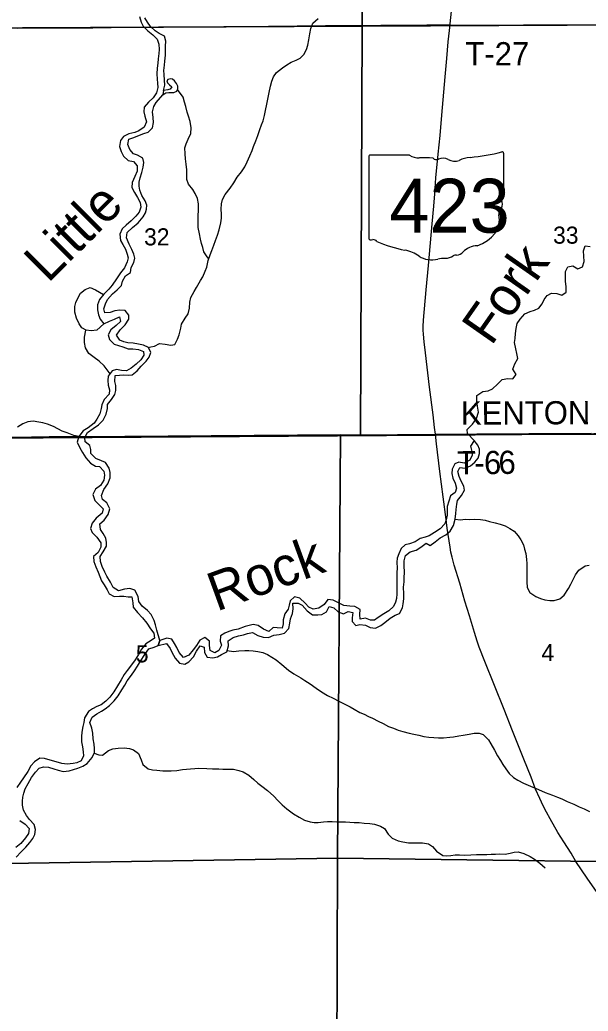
# Model space of a CAD drawing. Extents: x 1584893 to 1934202, y 663575 to 1091909.
# Drawn here: x 1783850 to 1791189, y 956462 to 969270 of the extents above; entities that cross this region are included whole.
import ezdxf

# ---------------------------------------------------------------- set-up
doc = ezdxf.new("R2010")
doc.units = 0
for name, color, linetype in [('GM_X_County_Road', 7, 'Continuous'), ('GM_X_Major_River', 7, 'Continuous'), ('GM_X_Major_River_Text', 7, 'Continuous'), ('GM_X_Minor_River', 7, 'Continuous'), ('GM_X_Minor_River_Text', 7, 'Continuous'), ('GM_X_Section', 7, 'Continuous'), ('GM_X_Section_Text', 7, 'Continuous'), ('GM_X_State_Location', 7, 'Continuous'), ('GM_X_State_Route', 7, 'Continuous'), ('GM_X_State_Shield', 7, 'Continuous'), ('GM_X_Township', 7, 'Continuous'), ('GM_X_Township_Road', 7, 'Continuous'), ('GM_X_Township_Road_Text', 7, 'Continuous')]:
    doc.layers.add(name, color=color, linetype=linetype)

msp = doc.modelspace()

# ---------------------------------------------------------------- linework, layer by layer
at = {"layer": 'GM_X_County_Road'}
for points in [[(1783824, 969162), (1784272, 969167), (1784527, 969169), (1784793, 969169), (1785030, 969172), (1785384, 969174), (1785703, 969176), (1786065, 969181), (1786486, 969184), (1786779, 969186), (1787060, 969189), (1787430, 969192), (1787798, 969196), (1788111, 969198), (1788512, 969201), (1789106, 969205), (1789300, 969205), (1789365, 969205), (1789406, 969205)], [(1781619, 963852), (1781621, 963852), (1781735, 963853), (1782030, 963855), (1782178, 963857), (1782375, 963858), (1782885, 963865), (1782998, 963866), (1783259, 963870), (1783766, 963878), (1784229, 963886), (1784853, 963887), (1785298, 963887), (1786047, 963891), (1786409, 963894), (1786805, 963898), (1787527, 963903), (1787855, 963906), (1788059, 963907), (1788529, 963910), (1788725, 963914), (1789216, 963917)]]:
    msp.add_lwpolyline(points, dxfattribs=at)
at = {"layer": 'GM_X_Major_River'}
for points in [[(1785394, 969315), (1785417, 969241), (1785443, 969190), (1785503, 969126), (1785568, 969075), (1785624, 969019), (1785644, 968958), (1785647, 968886), (1785643, 968834), (1785636, 968766), (1785630, 968712), (1785625, 968646), (1785621, 968574), (1785624, 968502), (1785628, 968452), (1785631, 968395), (1785613, 968325), (1785570, 968262), (1785512, 968206), (1785457, 968144), (1785451, 968080), (1785466, 968026), (1785484, 967954), (1785455, 967884), (1785385, 967838), (1785333, 967816), (1785259, 967799), (1785188, 967765), (1785148, 967713), (1785135, 967635), (1785157, 967571), (1785190, 967511), (1785248, 967454), (1785318, 967438), (1785366, 967383), (1785365, 967317), (1785337, 967245), (1785302, 967167), (1785297, 967103), (1785331, 967039), (1785369, 966976), (1785404, 966912), (1785412, 966852), (1785389, 966784), (1785347, 966732), (1785288, 966674), (1785222, 966617), (1785171, 966571), (1785143, 966501), (1785150, 966419), (1785178, 966368), (1785213, 966308), (1785235, 966244), (1785247, 966194), (1785238, 966142), (1785200, 966068), (1785149, 966000), (1785100, 965922), (1785044, 965842), (1784999, 965789), (1784933, 965725), (1784878, 965657), (1784852, 965587), (1784851, 965525), (1784865, 965461), (1784886, 965403), (1784936, 965342), (1785006, 965376), (1785073, 965401), (1785139, 965435), (1785150, 965371), (1785094, 965319)], [(1785705, 968359), (1785722, 968427), (1785718, 968489), (1785715, 968563), (1785711, 968617), (1785718, 968685), (1785724, 968735), (1785729, 968812), (1785731, 968862), (1785733, 968932), (1785736, 968996), (1785716, 969060), (1785649, 969095), (1785597, 969127), (1785539, 969186), (1785500, 969238), (1785464, 969294)], [(1785697, 968302), (1785737, 968325), (1785773, 968332), (1785803, 968332), (1785837, 968330), (1785877, 968348), (1785889, 968380), (1785890, 968412), (1785872, 968446), (1785848, 968482), (1785820, 968502), (1785800, 968510), (1785760, 968499), (1785746, 968481), (1785756, 968457), (1785782, 968432), (1785814, 968406), (1785793, 968374), (1785775, 968372), (1785761, 968368), (1785705, 968359)], [(1784934, 963204), (1784987, 963276), (1785017, 963352), (1785016, 963424), (1785004, 963480), (1784955, 963552), (1784903, 963571), (1784833, 963603), (1784765, 963668), (1784766, 963720), (1784752, 963772), (1784692, 963819), (1784689, 963875), (1784725, 963937), (1784796, 963990), (1784864, 964038), (1784927, 964098), (1784963, 964176), (1784980, 964248), (1784984, 964302), (1785035, 964367), (1785077, 964431), (1785088, 964483), (1785088, 964545), (1785075, 964596), (1785083, 964676), (1785135, 964679), (1785185, 964685), (1785249, 964681), (1785299, 964684), (1785364, 964734), (1785418, 964796), (1785483, 964859), (1785521, 964911), (1785542, 964971), (1785510, 965038), (1785448, 965066), (1785384, 965082), (1785314, 965095), (1785246, 965099), (1785194, 965108), (1785141, 965130), (1785097, 965197), (1785146, 965266), (1785208, 965330), (1785259, 965402), (1785257, 965454), (1785211, 965513), (1785141, 965521), (1785075, 965511), (1785015, 965490), (1784947, 965484), (1784933, 965535), (1784954, 965603), (1784982, 965658), (1785045, 965730), (1785105, 965782), (1785164, 965840), (1785176, 965896), (1785215, 965961), (1785277, 966007), (1785288, 966069), (1785320, 966137), (1785333, 966189), (1785323, 966241), (1785295, 966304), (1785260, 966374), (1785227, 966454), (1785237, 966522), (1785306, 966588), (1785378, 966648), (1785441, 966723), (1785473, 966775), (1785486, 966825), (1785488, 966877), (1785470, 966930), (1785427, 967002), (1785399, 967068), (1785392, 967121), (1785390, 967175), (1785404, 967227), (1785427, 967297), (1785444, 967367), (1785452, 967425), (1785440, 967481), (1785371, 967523), (1785319, 967540), (1785269, 967596), (1785244, 967661), (1785256, 967727), (1785324, 967752), (1785395, 967780), (1785449, 967801), (1785505, 967819), (1785563, 967873), (1785578, 967945), (1785570, 968007), (1785563, 968081), (1785581, 968149), (1785612, 968201), (1785697, 968302)], [(1785705, 968359), (1785697, 968302)], [(1785094, 965319), (1785023, 965265), (1784989, 965199), (1785009, 965139), (1785068, 965079), (1785124, 965064), (1785180, 965046), (1785248, 965021), (1785308, 965019), (1785382, 965010), (1785446, 964986), (1785451, 964936), (1785411, 964876), (1785352, 964820), (1785288, 964771), (1785226, 964735), (1785162, 964739), (1785096, 964754), (1785044, 964734), (1784991, 964668), (1784987, 964610), (1784990, 964552), (1785006, 964490), (1785005, 964434), (1784937, 964364), (1784908, 964298), (1784900, 964248), (1784885, 964178), (1784845, 964112), (1784810, 964060), (1784734, 963997), (1784667, 963959), (1784611, 963889), (1784592, 963813), (1784626, 963741), (1784657, 963679), (1784701, 963612), (1784762, 963542), (1784828, 963503), (1784880, 963499), (1784934, 963440), (1784943, 963388), (1784935, 963322), (1784892, 963256), (1784828, 963207), (1784793, 963137), (1784819, 963062), (1784926, 962953), (1784912, 962895), (1784835, 962832), (1784785, 962766), (1784764, 962698), (1784784, 962648), (1784843, 962587), (1784895, 962515), (1784896, 962457), (1784860, 962389), (1784801, 962337), (1784805, 962271), (1784830, 962203), (1784860, 962134), (1784884, 962078), (1784905, 962024), (1784939, 961969), (1784976, 961907), (1785002, 961853), (1785066, 961818), (1785138, 961822), (1785192, 961823), (1785248, 961815), (1785298, 961815), (1785309, 961736), (1785315, 961680), (1785369, 961614), (1785434, 961543), (1785492, 961474), (1785539, 961402), (1785579, 961348), (1785588, 961280), (1785544, 961250), (1785476, 961208), (1785421, 961140), (1785384, 961072), (1785340, 961003), (1785277, 960921), (1785235, 960865), (1785198, 960813), (1785160, 960743), (1785111, 960664), (1785065, 960590), (1785010, 960520), (1784962, 960468), (1784899, 960421), (1784845, 960397), (1784789, 960369), (1784736, 960335), (1784686, 960254), (1784675, 960194), (1784663, 960140), (1784650, 960066), (1784644, 960013)], [(1785656, 961253), (1785619, 961385), (1785600, 961454), (1785584, 961510), (1785544, 961588), (1785499, 961639), (1785431, 961693), (1785386, 961756), (1785376, 961820), (1785335, 961900), (1785271, 961925), (1785203, 961913), (1785126, 961892), (1785057, 961934), (1785021, 962007), (1784974, 962083), (1784946, 962136), (1784915, 962206), (1784891, 962270), (1784887, 962338), (1784926, 962398), (1784967, 962468), (1784969, 962518), (1784959, 962572), (1784928, 962635), (1784892, 962685), (1784883, 962757), (1784937, 962807), (1784992, 962879), (1785010, 962953), (1784975, 963029), (1784917, 963072), (1784905, 963124), (1784934, 963204)], [(1785636, 961186), (1785656, 961253)], [(1783802, 958452), (1783866, 958522), (1783927, 958580), (1783979, 958641), (1784016, 958695), (1784044, 958747), (1784050, 958811), (1784035, 958873), (1783973, 958940), (1783934, 958990), (1783896, 959061), (1783885, 959125), (1783883, 959175), (1783889, 959227), (1783900, 959281), (1783918, 959335), (1783957, 959405), (1783999, 959481), (1784052, 959549), (1784100, 959602), (1784157, 959620), (1784221, 959614), (1784288, 959593), (1784344, 959575), (1784410, 959560), (1784488, 959568), (1784541, 959583), (1784597, 959601), (1784663, 959627), (1784719, 959662), (1784782, 959738), (1784814, 959804), (1784813, 959858), (1784809, 959912), (1784796, 959980), (1784792, 960053), (1784781, 960119), (1784755, 960193), (1784784, 960261), (1784846, 960305), (1784903, 960340), (1784953, 960370), (1785007, 960412), (1785070, 960473), (1785118, 960535), (1785169, 960613), (1785205, 960675), (1785238, 960729), (1785292, 960803), (1785331, 960858), (1785371, 960918), (1785408, 960986), (1785463, 961070), (1785517, 961142), (1785583, 961167), (1785636, 961186)], [(1784644, 960013), (1784645, 959943), (1784659, 959879), (1784668, 959815), (1784674, 959761), (1784640, 959697), (1784587, 959671), (1784537, 959662), (1784461, 959654), (1784393, 959661), (1784321, 959685), (1784241, 959706), (1784169, 959726), (1784107, 959729), (1784039, 959685), (1783992, 959633), (1783954, 959559), (1783899, 959478), (1783857, 959422), (1783812, 959352)], [(1783849, 958925), (1783919, 958878), (1783970, 958824), (1783960, 958756), (1783923, 958702), (1783863, 958630), (1783800, 958576)]]:
    msp.add_lwpolyline(points, dxfattribs=at)
at = {"layer": 'GM_X_Minor_River'}
for points in [[(1785508, 965039), (1785540, 965047), (1785590, 965055), (1785655, 965089), (1785727, 965078), (1785799, 965066), (1785853, 965075), (1785887, 965145), (1785906, 965201), (1785928, 965287), (1785939, 965337), (1785987, 965417), (1786022, 965471), (1786040, 965547), (1786045, 965623), (1786060, 965683), (1786100, 965761), (1786133, 965813), (1786181, 965901), (1786214, 965952), (1786244, 966024), (1786263, 966076), (1786283, 966162), (1786306, 966232), (1786328, 966290), (1786357, 966358), (1786377, 966418), (1786404, 966490), (1786426, 966556), (1786445, 966646), (1786452, 966706), (1786454, 966760), (1786450, 966825), (1786455, 966891), (1786465, 966947), (1786502, 967013), (1786565, 967094), (1786613, 967164), (1786658, 967236), (1786714, 967306), (1786755, 967370), (1786787, 967435), (1786820, 967515), (1786848, 967583), (1786869, 967635), (1786897, 967705), (1786924, 967777), (1786951, 967853), (1786971, 967913), (1786991, 967967), (1787008, 968035), (1787022, 968101), (1787039, 968179), (1787054, 968247), (1787070, 968333), (1787087, 968413), (1787105, 968477), (1787126, 968533), (1787166, 968589), (1787243, 968649), (1787297, 968688), (1787355, 968722), (1787418, 968750), (1787468, 968777), (1787518, 968823), (1787551, 968885), (1787571, 968943), (1787582, 969013), (1787594, 969089), (1787607, 969159), (1787635, 969227), (1787702, 969287)], [(1786290, 966182), (1786270, 966209), (1786228, 966273), (1786212, 966327), (1786197, 966379), (1786183, 966438), (1786170, 966504), (1786154, 966588), (1786153, 966660), (1786153, 966736), (1786156, 966811), (1786159, 966891), (1786143, 966961), (1786116, 967027), (1786082, 967078), (1786028, 967148), (1786007, 967206), (1786008, 967333), (1785998, 967407), (1785989, 967475), (1785985, 967541), (1785982, 967617), (1785996, 967669), (1786025, 967729), (1786057, 967803), (1786064, 967875), (1786050, 967958), (1786029, 968024), (1786009, 968078), (1785994, 968152), (1785978, 968207), (1785961, 968269), (1785886, 968370)], [(1789717, 963836), (1789632, 963927), (1789628, 963977), (1789695, 964046), (1789749, 964118), (1789774, 964202), (1789762, 964278), (1789753, 964345), (1789753, 964415), (1789828, 964468), (1789896, 964478), (1789952, 964501), (1790019, 964561), (1790079, 964625), (1790151, 964636), (1790215, 964634), (1790260, 964686), (1790218, 964758), (1790243, 964826), (1790281, 964894), (1790270, 964958), (1790256, 965020), (1790239, 965101), (1790245, 965153), (1790252, 965219), (1790258, 965283), (1790273, 965349), (1790313, 965405), (1790372, 965472), (1790440, 965502), (1790498, 965520), (1790551, 965543), (1790595, 965601), (1790621, 965655), (1790658, 965707), (1790716, 965739), (1790784, 965734), (1790848, 965714), (1790904, 965751), (1790905, 965821), (1790897, 965896), (1790896, 965962), (1790898, 966020), (1790927, 966078), (1790991, 966091), (1791055, 966053), (1791117, 966077), (1791138, 966147), (1791134, 966217), (1791129, 966287), (1791149, 966351), (1791217, 966340)], [(1784936, 965342), (1784845, 965259), (1784773, 965251), (1784705, 965260), (1784651, 965292), (1784616, 965342), (1784582, 965417), (1784559, 965493), (1784559, 965565), (1784574, 965617), (1784598, 965673), (1784633, 965737), (1784695, 965787), (1784759, 965810), (1784825, 965780), (1784929, 965720)], [(1785015, 964698), (1784989, 964733), (1784938, 964799), (1784874, 964862), (1784811, 964906), (1784743, 964961), (1784699, 965031), (1784686, 965101), (1784684, 965170), (1784701, 965262)], [(1784610, 963887), (1784545, 963900), (1784461, 963933), (1784397, 963957), (1784341, 963988), (1784283, 964016), (1784206, 964047), (1784148, 964063), (1784094, 964073), (1784020, 964084), (1783952, 964076), (1783889, 964051), (1783819, 964009)], [(1789717, 963836), (1789670, 963760)], [(1789786, 963723), (1789765, 963775), (1789717, 963836)], [(1785636, 961186), (1785744, 961212), (1785791, 961150), (1785813, 961100), (1785855, 961025), (1785910, 960959), (1785980, 960946), (1786032, 960974), (1786093, 961041), (1786133, 961115), (1786178, 961183), (1786230, 961167), (1786235, 961097), (1786271, 961036), (1786341, 961028), (1786401, 961041), (1786455, 961069), (1786522, 961107), (1786544, 961183), (1786539, 961245), (1786605, 961288), (1786675, 961312), (1786740, 961326), (1786790, 961341), (1786856, 961353), (1786924, 961318), (1786994, 961296), (1787062, 961291), (1787132, 961321), (1787198, 961330), (1787266, 961348), (1787323, 961406), (1787335, 961474), (1787346, 961530), (1787372, 961600), (1787381, 961662), (1787377, 961734), (1787445, 961733), (1787497, 961709), (1787561, 961636), (1787630, 961584), (1787698, 961581), (1787748, 961587), (1787809, 961623), (1787845, 961691), (1787903, 961674), (1787961, 961620), (1788031, 961595), (1788091, 961625), (1788151, 961614), (1788142, 961546), (1788142, 961496), (1788190, 961446), (1788242, 961459), (1788314, 961449), (1788376, 961420), (1788442, 961410), (1788512, 961445), (1788562, 961485), (1788633, 961539), (1788697, 961578), (1788751, 961602), (1788790, 961674), (1788802, 961726), (1788809, 961788), (1788807, 961854), (1788806, 961940), (1788811, 962008), (1788815, 962063), (1788817, 962135), (1788814, 962215), (1788815, 962279), (1788831, 962349), (1788891, 962395), (1788966, 962420), (1789030, 962458), (1789095, 962509), (1789148, 962477), (1789215, 962527), (1789279, 962578), (1789352, 962618), (1789408, 962664), (1789449, 962739), (1789471, 962821), (1789482, 962894), (1789484, 962946), (1789491, 963012), (1789501, 963062), (1789552, 963124), (1789592, 963193), (1789584, 963244), (1789549, 963312), (1789525, 963372), (1789504, 963436), (1789534, 963488), (1789602, 963476), (1789671, 963507), (1789727, 963557), (1789767, 963609), (1789788, 963667), (1789786, 963723)], [(1789670, 963760), (1789686, 963694), (1789692, 963644), (1789659, 963582), (1789587, 963542), (1789517, 963555), (1789467, 963535), (1789434, 963467), (1789430, 963407), (1789441, 963347), (1789471, 963286), (1789490, 963218), (1789470, 963164), (1789413, 963120), (1789389, 963052), (1789370, 962984), (1789368, 962922), (1789369, 962872), (1789357, 962812), (1789339, 962760), (1789278, 962693), (1789204, 962647), (1789137, 962603), (1789083, 962588), (1789019, 962570), (1788953, 962528), (1788882, 962499), (1788826, 962487), (1788774, 962440), (1788745, 962370), (1788723, 962314), (1788720, 962264), (1788724, 962187), (1788719, 962129), (1788718, 961975), (1788720, 961909), (1788719, 961855), (1788713, 961795), (1788702, 961745), (1788674, 961691), (1788614, 961633), (1788551, 961595), (1788479, 961550), (1788428, 961512), (1788378, 961514), (1788313, 961541), (1788244, 961525), (1788239, 961586), (1788243, 961650), (1788176, 961692), (1788112, 961693), (1788034, 961703), (1787958, 961742), (1787894, 961772), (1787826, 961781), (1787779, 961717), (1787709, 961669), (1787637, 961658), (1787583, 961682), (1787535, 961733), (1787464, 961799), (1787398, 961814), (1787339, 961764), (1787329, 961706), (1787317, 961656), (1787270, 961594), (1787249, 961518), (1787251, 961466), (1787237, 961412), (1787171, 961417), (1787121, 961419), (1787066, 961369), (1786996, 961396), (1786929, 961444), (1786863, 961457), (1786813, 961445), (1786758, 961432), (1786668, 961396), (1786602, 961383), (1786548, 961367), (1786496, 961347), (1786441, 961312), (1786435, 961243), (1786452, 961193), (1786418, 961123), (1786368, 961094), (1786308, 961122), (1786300, 961186), (1786297, 961242), (1786239, 961291), (1786173, 961255), (1786130, 961187), (1786090, 961130), (1786031, 961060), (1785963, 961030), (1785909, 961095), (1785876, 961163), (1785846, 961214), (1785814, 961268), (1785748, 961282), (1785656, 961253)], [(1789471, 962821), (1789535, 962811), (1789605, 962817), (1789659, 962816), (1789719, 962818), (1789799, 962813), (1789857, 962805), (1789915, 962788), (1789987, 962772), (1790053, 962755), (1790119, 962733), (1790177, 962700), (1790235, 962662), (1790286, 962605), (1790320, 962553), (1790354, 962489), (1790369, 962430), (1790383, 962374), (1790392, 962300), (1790398, 962248), (1790399, 962174), (1790399, 962122), (1790396, 962070), (1790398, 962009), (1790403, 961935), (1790437, 961871), (1790513, 961818), (1790574, 961792), (1790628, 961777), (1790696, 961769), (1790750, 961770), (1790823, 961790), (1790879, 961838), (1790934, 961923), (1790964, 961979), (1791025, 962099), (1791070, 962159), (1791150, 962217), (1791204, 962224)], [(1785656, 961253), (1785636, 961186)], [(1786527, 961124), (1786608, 961110), (1786680, 961120), (1786754, 961121), (1786806, 961121), (1786864, 961116), (1786922, 961110), (1786986, 961095), (1787046, 961071), (1787102, 961034), (1787158, 961002), (1787233, 960943), (1787321, 960867), (1787390, 960820), (1787480, 960769), (1787532, 960735), (1787598, 960690), (1787675, 960636), (1787745, 960587), (1787823, 960540), (1787894, 960506), (1787968, 960467), (1788040, 960433), (1788114, 960394), (1788166, 960364), (1788239, 960323), (1788297, 960299), (1788353, 960270), (1788405, 960246), (1788477, 960211), (1788541, 960177), (1788612, 960142), (1788674, 960118), (1788736, 960091), (1788796, 960075), (1788876, 960056), (1788936, 960042), (1789002, 960027), (1789066, 960013), (1789130, 960002), (1789196, 959996), (1789256, 959993), (1789322, 959995), (1789402, 960002), (1789452, 960006), (1789520, 960018), (1789576, 960029), (1789651, 960043), (1789719, 960052), (1789781, 960054), (1789835, 960039), (1789900, 959969), (1789932, 959918), (1789981, 959836), (1790019, 959760), (1790058, 959699), (1790088, 959649), (1790128, 959592), (1790167, 959532), (1790223, 959480), (1790279, 959445), (1790354, 959406), (1790446, 959370), (1790546, 959327), (1790634, 959286), (1790730, 959254), (1790792, 959229), (1790849, 959207), (1790919, 959172), (1791003, 959135), (1791075, 959103), (1791139, 959078), (1791207, 959044)], [(1784810, 959795), (1784868, 959773), (1784918, 959769), (1784995, 959829), (1785051, 959850), (1785119, 959860), (1785195, 959863), (1785265, 959855), (1785317, 959838), (1785383, 959792), (1785416, 959710), (1785438, 959651), (1785506, 959595), (1785564, 959582), (1785620, 959576), (1785696, 959569), (1785746, 959567), (1785806, 959566), (1785878, 959572), (1785950, 959584), (1786000, 959591), (1786054, 959593), (1786110, 959596), (1786162, 959600), (1786264, 959599), (1786336, 959595), (1786420, 959592), (1786470, 959590), (1786542, 959589), (1786610, 959587), (1786680, 959572), (1786736, 959556), (1786808, 959511), (1786872, 959455), (1786923, 959408), (1786977, 959368), (1787047, 959313), (1787132, 959241), (1787180, 959186), (1787238, 959130), (1787299, 959075), (1787385, 959014), (1787455, 958968), (1787524, 958931), (1787598, 958909), (1787650, 958902), (1787702, 958902), (1787770, 958908), (1787825, 958911), (1787885, 958913), (1787945, 958910), (1788005, 958910), (1788057, 958908), (1788111, 958905), (1788169, 958901), (1788231, 958898), (1788297, 958892), (1788369, 958885), (1788429, 958877), (1788509, 958854), (1788561, 958824), (1788608, 958751), (1788660, 958699), (1788737, 958662), (1788795, 958650), (1788871, 958639), (1788933, 958637), (1788995, 958636), (1789050, 958638), (1789126, 958623), (1789179, 958591), (1789229, 958531), (1789311, 958472), (1789361, 958470), (1789417, 958473), (1789473, 958483), (1789527, 958482), (1789597, 958480), (1789675, 958481), (1789745, 958485), (1789809, 958486), (1789881, 958488), (1789937, 958490), (1789991, 958491), (1790049, 958493), (1790117, 958492), (1790182, 958502), (1790232, 958518), (1790284, 958519), (1790360, 958499), (1790439, 958460), (1790495, 958428), (1790567, 958373), (1790633, 958316)]]:
    msp.add_lwpolyline(points, dxfattribs=at)
at = {"layer": 'GM_X_Section'}
for points in [[(1783012, 974453), (1788243, 974478), (1788271, 969190), (1783001, 969162)], [(1788243, 974478), (1793492, 974494), (1793564, 969214), (1788271, 969190)], [(1783001, 969162), (1788271, 969190), (1788251, 963905), (1787989, 963907), (1782977, 963870)], [(1788271, 969190), (1793564, 969214), (1793544, 963925), (1793458, 963926), (1788251, 963905)], [(1782977, 963870), (1787989, 963907), (1787951, 958441), (1782893, 958359), (1782913, 963870)], [(1788251, 963905), (1793458, 963926), (1793301, 958370), (1787951, 958441), (1787989, 963907)], [(1782893, 958359), (1787951, 958441), (1787937, 953135), (1782828, 953094)], [(1787951, 958441), (1793301, 958370), (1793212, 953051), (1787937, 953135)]]:
    msp.add_lwpolyline(points, close=True, dxfattribs=at)
at = {"layer": 'GM_X_State_Route'}
msp.add_lwpolyline([(1791435, 957810), (1791177, 958180), (1791030, 958398), (1790969, 958503), (1790876, 958650), (1790799, 958772), (1790698, 958948), (1790652, 959033), (1790610, 959117), (1790564, 959212), (1790511, 959331), (1790451, 959484), (1790360, 959718), (1790214, 960083), (1790105, 960359), (1789853, 960981), (1789782, 961166), (1789755, 961244), (1789721, 961354), (1789655, 961568), (1789598, 961759), (1789530, 961990), (1789460, 962226), (1789432, 962330), (1789417, 962394), (1789405, 962458), (1789370, 962702), (1789355, 962816), (1789315, 963109), (1789275, 963434), (1789231, 963793), (1789216, 963917), (1789205, 964005), (1789187, 964168), (1789141, 964526), (1789088, 964966), (1789071, 965112), (1789062, 965211), (1789060, 965260), (1789060, 965309), (1789064, 965392), (1789096, 965784), (1789126, 966095), (1789173, 966634), (1789194, 966863), (1789207, 967023), (1789224, 967229), (1789253, 967535), (1789277, 967778), (1789300, 968040), (1789343, 968532), (1789362, 968772), (1789383, 968985), (1789406, 969205), (1789407, 969217), (1789446, 969592)], dxfattribs=at)
at = {"layer": 'GM_X_State_Shield'}
for p, q in [((1788884, 967522), (1788374, 967522)), ((1790098, 966995), (1790098, 967548)), ((1788357, 967503), (1788357, 966447)), ((1790097, 966995), (1790098, 966995))]:
    msp.add_line(p, q, dxfattribs=at)
for centre, major_axis, start_param, end_param in [((1788377, 967506), (20.2, 0), 1.712693, 3.28349), ((1789005, 967644), (196, 0), 4.042523, 4.731795), ((1789478, 968962), (1845, 0), 4.814394, 5.042369), ((1790078, 967550), (19.4, 0), 6.141152, 7.989035), ((1789070, 966928), (702, 0), 1.404758, 1.657858), ((1789230, 967511), (56.4, 0), 3.836095, 5.185415), ((1789312, 967389), (117, 0), 0.950623, 2.079405), ((1789464, 967557), (141, 0), 4.081561, 5.145723), ((1789713, 967199), (371, 0), 1.699011, 2.107814), ((1790093, 966955), (30, 0), 1.883978, 3.671073), ((1789902, 966885), (180, 0), 5.934695, 6.695948), ((1790077, 966993), (20.7, 0), 5.05454, 6.418171), ((1789581, 966693), (462, 0), 5.101752, 6.440018), ((1790167, 966764), (131, 0), 2.387724, 3.262537), ((1788377, 966445), (20.3, 0), 3.00124, 4.508301), ((1788381, 966553), (155, 0), 4.665946, 4.897461), ((1788412, 966386), (56, 0), 0.519207, 1.627899), ((1789119, 967335), (1333, 0), 4.195997, 4.488961), ((1788722, 965972), (417, 0), 0.823519, 1.323587), ((1789455, 966344), (149, 0), 4.937069, 5.64225), ((1789776, 966150), (253, 0), 1.647645, 2.488434), ((1789173, 966381), (265, 0), 4.026481, 4.996735), ((1789325, 966015), (217, 0), 1.495662, 1.94098), ((1789345, 966302), (141, 0), 4.691044, 5.507374), ((1789472, 966199), (39.7, 0), 1.147584, 2.315152)]:
    msp.add_ellipse(centre, major_axis=major_axis, ratio=0.8, start_param=start_param, end_param=end_param, dxfattribs=at)
at = {"layer": 'GM_X_Township'}
for points in [[(1809470, 974481), (1809409, 966524), (1809397, 965194), (1809388, 963837), (1808803, 963840), (1808767, 963841), (1804088, 963866), (1803095, 963873), (1802091, 963913), (1801944, 963913), (1800576, 963924), (1795449, 963933), (1794326, 963949), (1789219, 963906), (1781614, 963853)], [(1777226, 952294), (1777326, 958526), (1777421, 963835), (1779496, 963806), (1780304, 963849), (1781614, 963853), (1789219, 963906), (1794326, 963949), (1795449, 963933), (1800576, 963924), (1801944, 963913), (1802091, 963913), (1803095, 963873), (1804088, 963866), (1808767, 963841), (1808803, 963840), (1809388, 963837), (1809358, 958555), (1809298, 953687)]]:
    msp.add_lwpolyline(points, dxfattribs=at)
at = {"layer": 'GM_X_Township_Road'}
for points in [[(1789406, 969205), (1789517, 969203), (1789670, 969202), (1789752, 969202), (1790078, 969203), (1790354, 969204), (1790597, 969204), (1790791, 969205), (1791130, 969207), (1791455, 969208), (1791672, 969209), (1791968, 969210), (1792254, 969212), (1792590, 969216), (1793094, 969218), (1793292, 969221), (1793567, 969225), (1793852, 969225), (1794192, 969224)], [(1789216, 963917), (1789249, 963917), (1789323, 963917), (1789520, 963919), (1789750, 963922), (1789980, 963922), (1790144, 963923), (1790423, 963925), (1790604, 963926), (1790768, 963927), (1791228, 963928)]]:
    msp.add_lwpolyline(points, dxfattribs=at)

# ---------------------------------------------------------------- texts
at = {"layer": 'GM_X_Major_River_Text'}
msp.add_text('Little', height=500.1, rotation=45.0145, dxfattribs=at).set_placement((1784214, 965858))
at = {"layer": 'GM_X_Minor_River_Text'}
for s, rotation, p in [('Fork', 55.0137, (1789938, 965046)), ('Rock', 20.0139, (1786390, 961623))]:
    msp.add_text(s, height=500.1, rotation=rotation, dxfattribs=at).set_placement(p)
at = {"layer": 'GM_X_Section_Text'}
for s, p in [('32', (1785454, 966356)), ('33', (1790736, 966378)), ('5', (1785348, 960969)), ('4', (1790586, 960985))]:
    msp.add_text(s, height=221, rotation=0, dxfattribs=at).set_placement(p)
at = {"layer": 'GM_X_State_Location'}
for s in ['s', 'r']:
    msp.add_text(s, height=1, dxfattribs=at).set_placement((1789208, 966905))
msp.add_text('423', height=1, rotation=0, dxfattribs=at).set_placement((1788855, 966832))
at = {"layer": 'GM_X_State_Shield'}
msp.add_text('423', height=696.1, dxfattribs=at).set_placement((1788623, 966521))
at = {"layer": 'GM_X_Township_Road_Text'}
for s, rotation, p in [('T-27', 0, (1789603, 968682)), ('KENTON', 0.1671, (1789546, 964040)), ('T', 0.39, (1789496, 963397)), ('6', 0.5411, (1789845, 963400)), ('6', 1.291, (1790034, 963401)), ('-', 0.4189, (1789721, 963399))]:
    msp.add_text(s, height=300, rotation=rotation, dxfattribs=at).set_placement(p)

doc.saveas('drawing.dxf')
